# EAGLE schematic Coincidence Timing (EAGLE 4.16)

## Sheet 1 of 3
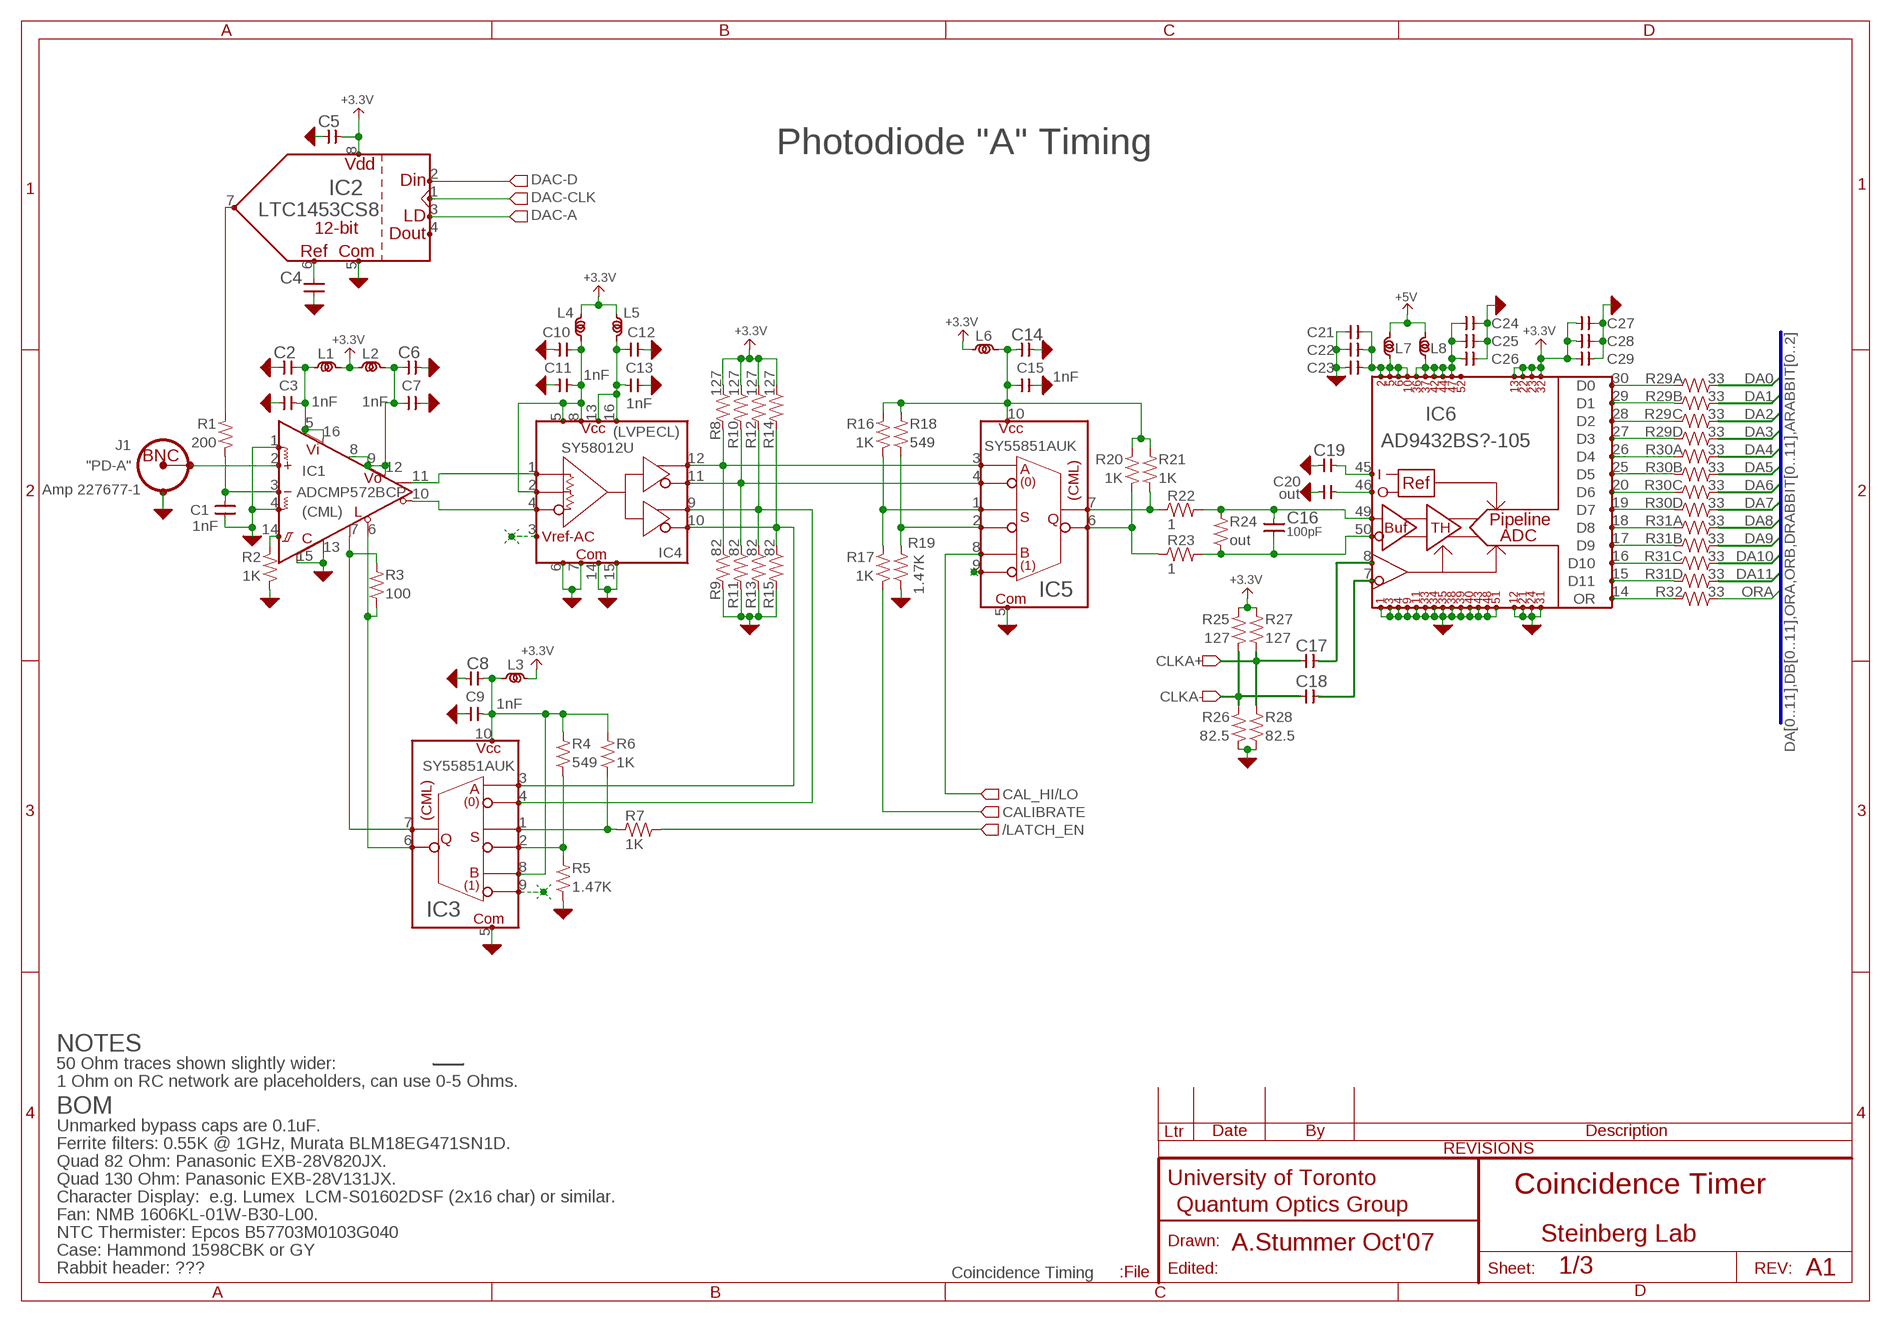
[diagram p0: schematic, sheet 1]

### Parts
C1  1nF  CAP-V-0603  [1608(0603)]
C2  CAP-H-0603  [1608(0603)]
C3  1nF  CAP-H-0603  [1608(0603)]
C4  CAP-V-0603  [1608(0603)]
C5  CAP-H-0603  [1608(0603)]
C6  CAP-H-0603  [1608(0603)]
C7  1nF  CAP-H-0603  [1608(0603)]
C8  CAP-H-0603  [1608(0603)]
C9  1nF  CAP-H-0603  [1608(0603)]
C10  CAP-H-0603  [1608(0603)]
C11  1nF  CAP-H-0603  [1608(0603)]
C12  CAP-H-0603  [1608(0603)]
C13  1nF  CAP-H-0603  [1608(0603)]
C14  CAP-H-0603  [1608(0603)]
C15  1nF  CAP-H-0603  [1608(0603)]
C16  100pF  CAP-V-0603  [1608(0603)]
C17  CAP-H-0603  [1608(0603)]
C18  CAP-H-0603  [1608(0603)]
C19  CAP-H-0603  [1608(0603)]
C20  out  CAP-H-0603  [1608(0603)]
C21  CAP-H-0603  [1608(0603)]
C22  CAP-H-0603  [1608(0603)]
C23  CAP-H-0603  [1608(0603)]
C24  CAP-H-0603  [1608(0603)]
C25  CAP-H-0603  [1608(0603)]
C26  CAP-H-0603  [1608(0603)]
C27  CAP-H-0603  [1608(0603)]
C28  CAP-H-0603  [1608(0603)]
C29  CAP-H-0603  [1608(0603)]
IC1  ADCMP572BCP  ADCMP572-3-LFCSP16  [LFCSP-16]
IC2  LTC1453CS8  LTC145_(DAC12)  [SOIC-8]
IC3  SY55851AUK  SY55851(MICREL-MUX)-MSOP10  [MSOP10]
IC4  SY58012U  SY58011-3U(MICREL_1-2BUFFER)-MLF16  [MLF-16]
IC5  SY55851AUK  SY55851(MICREL-MUX)-MSOP10  [MSOP10]
IC6  AD9432BS?-105  AD9432  [QFP52]
J1  Amp 227677-1  CONN-BNCTYPE3HORIZ  [CONN-BNC-AMP-TYPE3HORIZ]
L1  INDUCTOR-0603  [1608(0603)]
L2  INDUCTOR-0603  [1608(0603)]
L3  INDUCTOR-0603  [1608(0603)]
L4  INDUCTOR-0603  [1608(0603)]
L5  INDUCTOR-0603  [1608(0603)]
L6  INDUCTOR-0603  [1608(0603)]
L7  INDUCTOR-0603  [1608(0603)]
L8  INDUCTOR-0603  [1608(0603)]
R1  200  R-V-0603  [1608(0603)]
R2  1K  R-V-0603  [1608(0603)]
R3  100  R-V-0603  [1608(0603)]
R4  549  R-V-0603  [1608(0603)]
R5  1.47K  R-V-0603  [1608(0603)]
R6  1K  R-V-0603  [1608(0603)]
R7  1K  R-H-0603  [1608(0603)]
R8  127  R-V-0402  [1005(0402)]
R9  82  R-V-0402  [1005(0402)]
R10  127  R-V-0402  [1005(0402)]
R11  82  R-V-0402  [1005(0402)]
R12  127  R-V-0402  [1005(0402)]
R13  82  R-V-0402  [1005(0402)]
R14  127  R-V-0402  [1005(0402)]
R15  82  R-V-0402  [1005(0402)]
R16  1K  R-V-0603  [1608(0603)]
R17  1K  R-V-0603  [1608(0603)]
R18  549  R-V-0603  [1608(0603)]
R19  1.47K  R-V-0603  [1608(0603)]
R20  1K  R-V-0603  [1608(0603)]
R21  1K  R-V-0603  [1608(0603)]
R22  1  R-H-0603  [1608(0603)]
R23  1  R-H-0603  [1608(0603)]
R24  out  R-V-0603  [1608(0603)]
R25  127  R-V-0603  [1608(0603)]
R26  82.5  R-V-0603  [1608(0603)]
R27  127  R-V-0603  [1608(0603)]
R28  82.5  R-V-0603  [1608(0603)]
R29  33  R-4PAK-0603  [PANASONIC_EXB-V8V(QUAD-R-PACK)]
R30  33  R-4PAK-0603  [PANASONIC_EXB-V8V(QUAD-R-PACK)]
R31  33  R-4PAK-0603  [PANASONIC_EXB-V8V(QUAD-R-PACK)]
R32  33  R-H-0805  [2012(0805)]

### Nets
+3.3V: C5.2 C27.2 C28.2 C29.2 IC2.8(VDD) IC6.13(VCCD1) IC6.22(VCCD2) IC6.23(VCCD3) IC6.32(VCCD4) L1.2(B) L2.1(A) L3.1(A) L4.1(A) L5.1(A) L6.1(A) R8.1 R10.1 R12.1 R14.1 R25.2 R27.2 ; also sheet 2,3
+5V: L7.2(B) L8.2(B) ; also sheet 2,3
/LATCH_EN: R7.2 ; also sheet 2,3
AGND: C1.1 C2.1 C3.1 C4.1 C5.1 C6.2 C7.1 C8.2 C9.1 C10.2 C11.1 C12.2 C13.1 C14.2 C15.1 C19.1 C20.1 C21.1 C22.1 C23.1 C24.1 C25.1 C26.1 C27.1 C28.1 C29.1 IC1.1(VPT) IC1.4(VNT) IC1.13(COM1) IC1.15(COM2) IC2.5(COM) IC3.5(COM) IC4.6(COM1) IC4.7(COM2) IC4.14(COM3) IC4.15(COM4) IC5.5(COM) IC6.1(AGND1) IC6.3(AGND2) IC6.4(AGND3) IC6.9(AGND4) IC6.11(AGND5) IC6.12(DGND1) IC6.21(DGND2) IC6.24(DGND3) IC6.31(DGND4) IC6.33(AGND6) IC6.34(AGND7) IC6.35(AGND8) IC6.38(AGND9) IC6.39(AGND10) IC6.40(AGND11) IC6.43(AGND12) IC6.48(AGND13) IC6.51(AGND14) J1.SHIELD R2.1 R5.1 R9.2 R11.2 R13.2 R15.2 R19.1 R26.1 R28.1 ; also sheet 2,3
CAL_HI/LO: IC5.8(B+) ; also sheet 2,3
CALIBRATE: R17.1 ; also sheet 2,3
CLKA+ [50_Ohm]: C17.1 R27.1 R28.2 ; also sheet 3
CLKA- [50_Ohm]: C18.1 R25.1 R26.2 ; also sheet 3
DA0 [50_Ohm]: R29.1B ; also sheet 3
DA1 [50_Ohm]: R29.2B ; also sheet 3
DA2 [50_Ohm]: R29.3B ; also sheet 3
DA3 [50_Ohm]: R29.4B ; also sheet 3
DA4 [50_Ohm]: R30.1B ; also sheet 3
DA5 [50_Ohm]: R30.2B ; also sheet 3
DA6 [50_Ohm]: R30.3B ; also sheet 3
DA7 [50_Ohm]: R30.4B ; also sheet 3
DA8 [50_Ohm]: R31.1B ; also sheet 3
DA9 [50_Ohm]: R31.2B ; also sheet 3
DA10 [50_Ohm]: R31.3B ; also sheet 3
DA11 [50_Ohm]: R31.4B ; also sheet 3
DAC-A: IC2.3(CS/LD) ; also sheet 3
DAC-CLK: IC2.1(CLK) ; also sheet 2,3
DAC-D: IC2.2(DIN) ; also sheet 2,3
N$1: C1.2 IC1.3(VN) R1.1
N$2: IC1.2(VP) J1.CONDUCTOR
N$3: IC2.7(OUT) R1.2
N$4: IC3.3(A+) IC4.10(Q1-) R14.2 R15.1
N$5: C10.1 C11.2 IC4.2(INT) IC4.5(VCC1) IC4.8(VCC2) L4.2(B)
N$6: IC1.11(Q+) IC4.1(IN+)
N$7: IC1.14(HYS) R2.2
N$8: C2.2 C3.2 IC1.5(VCCI1) IC1.16(VCCI2) L1.1(A)
N$9: IC1.10(Q-) IC4.4(IN-)
N$11: C6.1 C7.2 IC1.8(VTT) IC1.9(VCCO1) IC1.12(VCCO2) L2.2(B)
N$12: IC3.4(A-) IC4.9(Q1+) R12.2 R13.1
N$13: C12.1 C13.2 IC4.13(VCC3) IC4.16(VCC4) L5.2(B)
N$14: IC1.7(LE+) IC3.7(Q+) R3.2
N$15: C14.1 C15.2 IC5.10(VCC) L6.2(B) R16.2 R18.2 R20.2 R21.2
N$16: IC5.2(S-) R18.1 R19.2
N$17 [50_Ohm]: IC5.7(Q+) R21.1 R22.1
N$18: IC1.6(LE-) IC3.6(Q-) R3.1
N$19: IC3.2(S-) R4.1 R5.2
N$20: IC3.1(S+) R6.1 R7.1
N$21: C8.1 C9.2 IC3.8(B+) IC3.10(VCC) L3.2(B) R4.2 R6.2
N$22 [50_Ohm]: IC5.6(Q-) R20.1 R23.1
N$23: IC5.1(S+) R16.1 R17.2
N$24: IC4.12(Q0+) IC5.3(A+) R8.2 R9.1
N$25: IC4.11(Q0-) IC5.4(A-) R10.2 R11.1
N$26 [50_Ohm]: C18.2 IC6.7(CLK-)
N$27 [50_Ohm]: C16.2 IC6.49(AIN+) R22.2 R24.2
N$28 [50_Ohm]: C16.1 IC6.50(AIN-) R23.2 R24.1
N$29 [50_Ohm]: C17.2 IC6.8(CLK+)
N$30: C24.2 C25.2 C26.2 IC6.36(VCCA5) IC6.37(VCCA6) IC6.42(VCCA7) IC6.44(VCCA8) IC6.52(VCCA10) L8.1(A)
N$32: C19.2 IC6.45(REF-IN)
N$33: C20.2 IC6.46(REF-OUT)
N$34: C21.2 C22.2 C23.2 IC6.2(VCCA1) IC6.5(VCCA2) IC6.6(VCCA3) IC6.10(VCCA4) L7.1(A)
N$35: IC6.30(D0) R29.1A
N$36: IC6.29(D1) R29.2A
N$37: IC6.28(D2) R29.3A
N$38: IC6.27(D3) R29.4A
N$39: IC6.26(D4) R30.1A
N$40: IC6.25(D5) R30.2A
N$41: IC6.20(D6) R30.3A
N$42: IC6.19(D7) R30.4A
N$43: IC6.18(D8) R31.1A
N$44: IC6.17(D9) R31.2A
N$45: IC6.16(D10) R31.3A
N$46: IC6.15(D11) R31.4A
N$47: C4.2 IC2.6(REF)
N$59: IC6.14(OR) R32.1
ORA: R32.2 ; also sheet 3
Unconnected: IC2.4(DOUT) IC3.9(B-) IC4.3(VREF-AC) IC5.9(B-) IC6.47(VCCA9)

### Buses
DA[0..11],DB[0..11],ORA,ORB,DRABBIT[0..11],ARABBIT[0..2]

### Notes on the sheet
- Photodiode "A" Timing
- (LVPECL)
- "PD-A"
- (CML)
- NOTES
- 50 Ohm traces shown slightly wider:
- 1 Ohm on RC network are placeholders, can use 0-5 Ohms.
- BOM
- Unmarked bypass caps are 0.1uF.
- Ferrite filters: 0.55K @ 1GHz, Murata BLM18EG471SN1D.
- Quad 82 Ohm: Panasonic EXB-28V820JX.
- Quad 130 Ohm: Panasonic EXB-28V131JX.
- Coincidence Timer
- Character Display:  e.g. Lumex  LCM-S01602DSF (2x16 char) or similar.
- Fan: NMB 1606KL-01W-B30-L00.
- NTC Thermister: Epcos B57703M0103G040 | Steinberg Lab
- A.Stummer Oct'07
- Case: Hammond 1598CBK or GY
- Rabbit header: ??? | A1

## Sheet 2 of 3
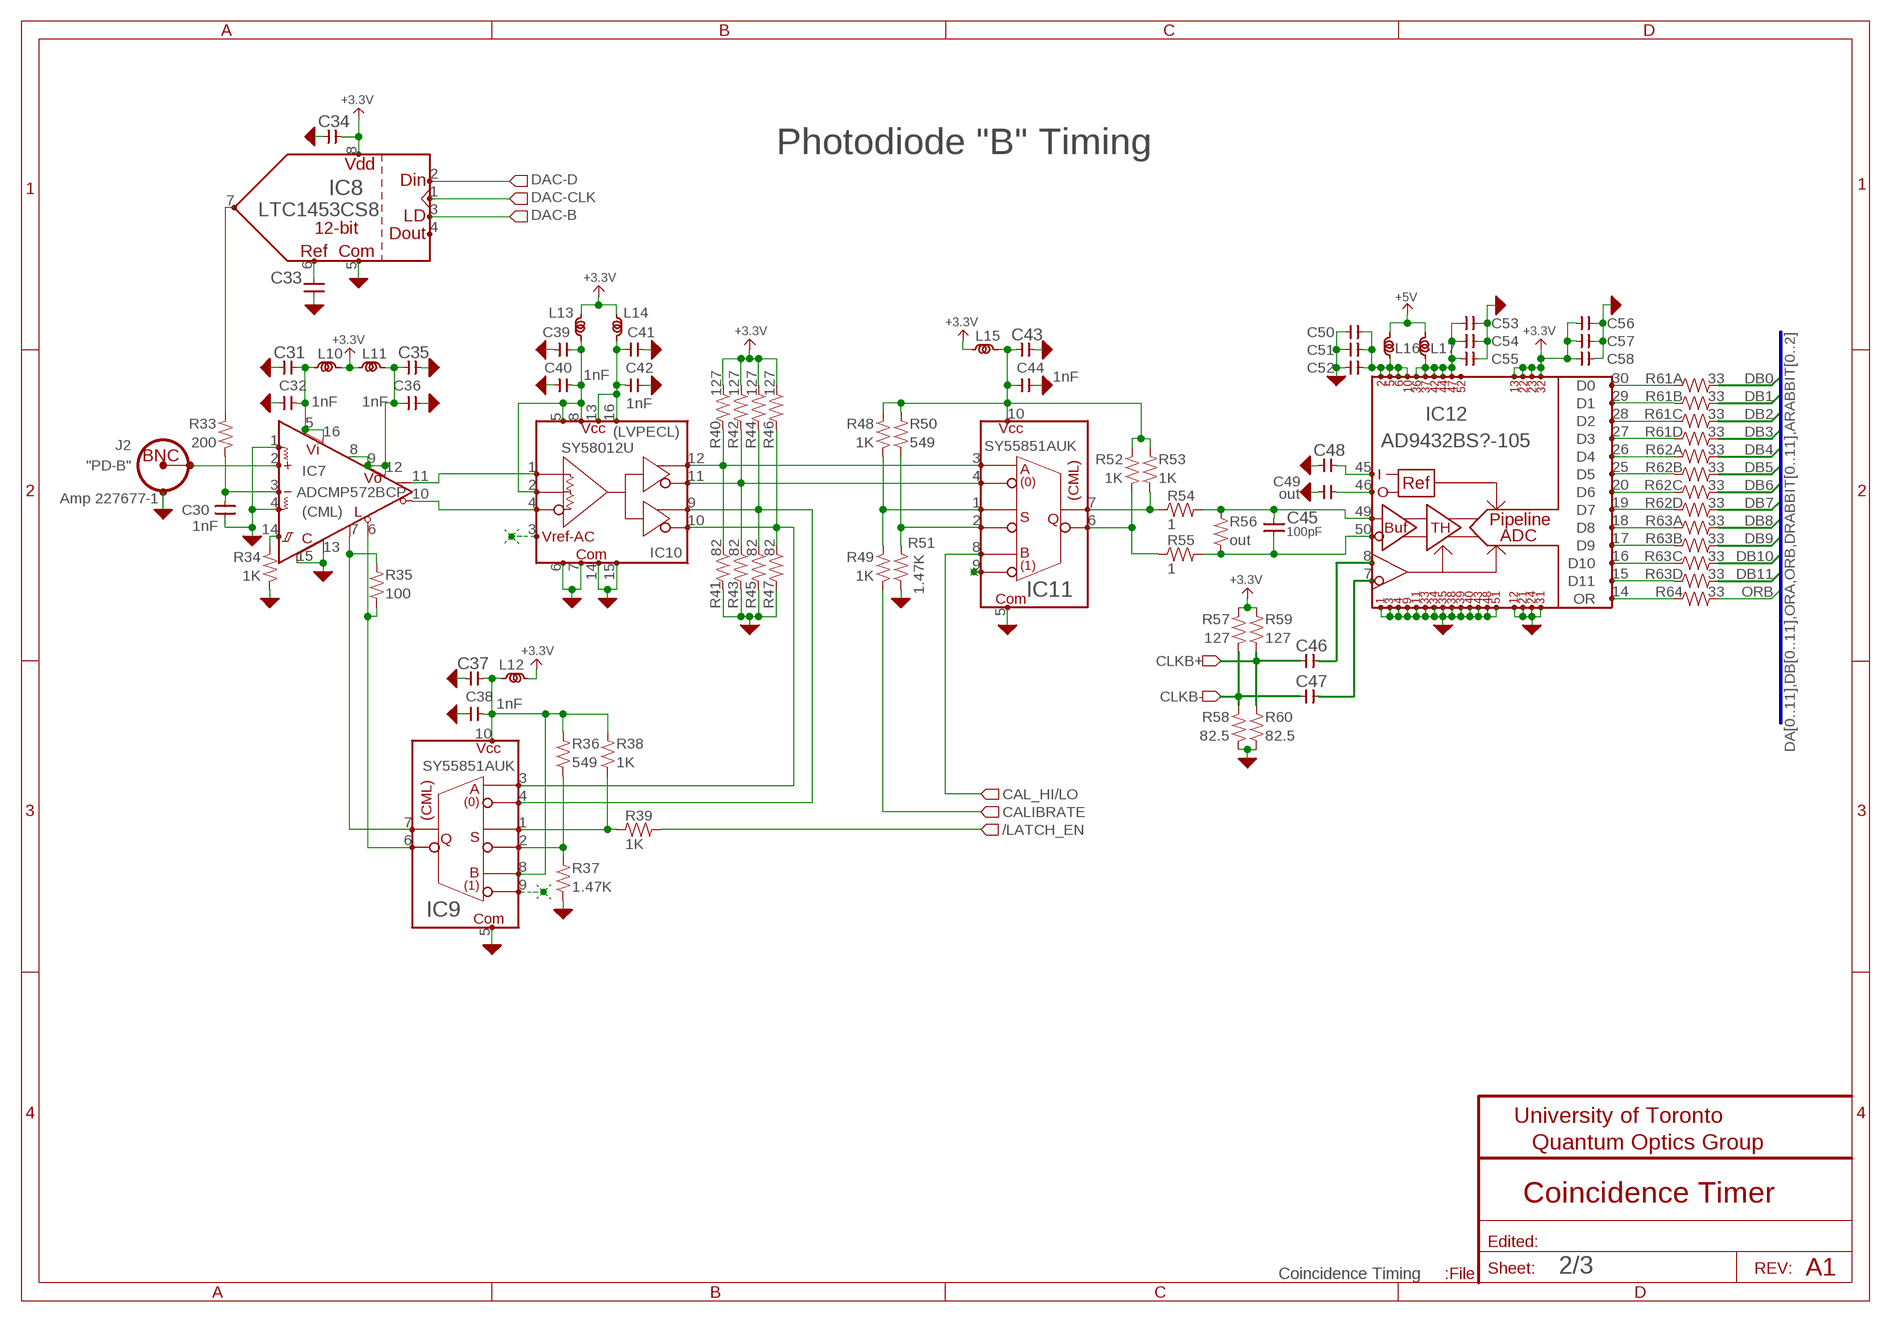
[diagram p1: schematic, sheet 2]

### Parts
C30  1nF  CAP-V-0603  [1608(0603)]
C31  CAP-H-0603  [1608(0603)]
C32  1nF  CAP-H-0603  [1608(0603)]
C33  CAP-V-0603  [1608(0603)]
C34  CAP-H-0603  [1608(0603)]
C35  CAP-H-0603  [1608(0603)]
C36  1nF  CAP-H-0603  [1608(0603)]
C37  CAP-H-0603  [1608(0603)]
C38  1nF  CAP-H-0603  [1608(0603)]
C39  CAP-H-0603  [1608(0603)]
C40  1nF  CAP-H-0603  [1608(0603)]
C41  CAP-H-0603  [1608(0603)]
C42  1nF  CAP-H-0603  [1608(0603)]
C43  CAP-H-0603  [1608(0603)]
C44  1nF  CAP-H-0603  [1608(0603)]
C45  100pF  CAP-V-0603  [1608(0603)]
C46  CAP-H-0603  [1608(0603)]
C47  CAP-H-0603  [1608(0603)]
C48  CAP-H-0603  [1608(0603)]
C49  out  CAP-H-0603  [1608(0603)]
C50  CAP-H-0603  [1608(0603)]
C51  CAP-H-0603  [1608(0603)]
C52  CAP-H-0603  [1608(0603)]
C53  CAP-H-0603  [1608(0603)]
C54  CAP-H-0603  [1608(0603)]
C55  CAP-H-0603  [1608(0603)]
C56  CAP-H-0603  [1608(0603)]
C57  CAP-H-0603  [1608(0603)]
C58  CAP-H-0603  [1608(0603)]
IC7  ADCMP572BCP  ADCMP572-3-LFCSP16  [LFCSP-16]
IC8  LTC1453CS8  LTC145_(DAC12)  [SOIC-8]
IC9  SY55851AUK  SY55851(MICREL-MUX)-MSOP10  [MSOP10]
IC10  SY58012U  SY58011-3U(MICREL_1-2BUFFER)-MLF16  [MLF-16]
IC11  SY55851AUK  SY55851(MICREL-MUX)-MSOP10  [MSOP10]
IC12  AD9432BS?-105  AD9432  [QFP52]
J2  Amp 227677-1  CONN-BNCTYPE3HORIZ  [CONN-BNC-AMP-TYPE3HORIZ]
L10  INDUCTOR-0603  [1608(0603)]
L11  INDUCTOR-0603  [1608(0603)]
L12  INDUCTOR-0603  [1608(0603)]
L13  INDUCTOR-0603  [1608(0603)]
L14  INDUCTOR-0603  [1608(0603)]
L15  INDUCTOR-0603  [1608(0603)]
L16  INDUCTOR-0603  [1608(0603)]
L17  INDUCTOR-0603  [1608(0603)]
R33  200  R-V-0603  [1608(0603)]
R34  1K  R-V-0603  [1608(0603)]
R35  100  R-V-0603  [1608(0603)]
R36  549  R-V-0603  [1608(0603)]
R37  1.47K  R-V-0603  [1608(0603)]
R38  1K  R-V-0603  [1608(0603)]
R39  1K  R-H-0603  [1608(0603)]
R40  127  R-V-0402  [1005(0402)]
R41  82  R-V-0402  [1005(0402)]
R42  127  R-V-0402  [1005(0402)]
R43  82  R-V-0402  [1005(0402)]
R44  127  R-V-0402  [1005(0402)]
R45  82  R-V-0402  [1005(0402)]
R46  127  R-V-0402  [1005(0402)]
R47  82  R-V-0402  [1005(0402)]
R48  1K  R-V-0603  [1608(0603)]
R49  1K  R-V-0603  [1608(0603)]
R50  549  R-V-0603  [1608(0603)]
R51  1.47K  R-V-0603  [1608(0603)]
R52  1K  R-V-0603  [1608(0603)]
R53  1K  R-V-0603  [1608(0603)]
R54  1  R-H-0603  [1608(0603)]
R55  1  R-H-0603  [1608(0603)]
R56  out  R-V-0603  [1608(0603)]
R57  127  R-V-0603  [1608(0603)]
R58  82.5  R-V-0603  [1608(0603)]
R59  127  R-V-0603  [1608(0603)]
R60  82.5  R-V-0603  [1608(0603)]
R61  33  R-4PAK-0603  [PANASONIC_EXB-V8V(QUAD-R-PACK)]
R62  33  R-4PAK-0603  [PANASONIC_EXB-V8V(QUAD-R-PACK)]
R63  33  R-4PAK-0603  [PANASONIC_EXB-V8V(QUAD-R-PACK)]
R64  33  R-H-0805  [2012(0805)]

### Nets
+3.3V: C34.2 C56.2 C57.2 C58.2 IC8.8(VDD) IC12.13(VCCD1) IC12.22(VCCD2) IC12.23(VCCD3) IC12.32(VCCD4) L10.2(B) L11.1(A) L12.1(A) L13.1(A) L14.1(A) L15.1(A) R40.1 R42.1 R44.1 R46.1 R57.2 R59.2 ; also sheet 1,3
+5V: L16.2(B) L17.2(B) ; also sheet 1,3
/LATCH_EN: R39.2 ; also sheet 1,3
AGND: C30.1 C31.1 C32.1 C33.1 C34.1 C35.2 C36.1 C37.2 C38.1 C39.2 C40.1 C41.2 C42.1 C43.2 C44.1 C48.1 C49.1 C50.1 C51.1 C52.1 C53.1 C54.1 C55.1 C56.1 C57.1 C58.1 IC7.1(VPT) IC7.4(VNT) IC7.13(COM1) IC7.15(COM2) IC8.5(COM) IC9.5(COM) IC10.6(COM1) IC10.7(COM2) IC10.14(COM3) IC10.15(COM4) IC11.5(COM) IC12.1(AGND1) IC12.3(AGND2) IC12.4(AGND3) IC12.9(AGND4) IC12.11(AGND5) IC12.12(DGND1) IC12.21(DGND2) IC12.24(DGND3) IC12.31(DGND4) IC12.33(AGND6) IC12.34(AGND7) IC12.35(AGND8) IC12.38(AGND9) IC12.39(AGND10) IC12.40(AGND11) IC12.43(AGND12) IC12.48(AGND13) IC12.51(AGND14) J2.SHIELD R34.1 R37.1 R41.2 R43.2 R45.2 R47.2 R51.1 R58.1 R60.1 ; also sheet 1,3
CAL_HI/LO: IC11.8(B+) ; also sheet 1,3
CALIBRATE: R49.1 ; also sheet 1,3
CLKB+ [50_Ohm]: C46.1 R59.1 R60.2 ; also sheet 3
CLKB- [50_Ohm]: C47.1 R57.1 R58.2 ; also sheet 3
DAC-B: IC8.3(CS/LD) ; also sheet 3
DAC-CLK: IC8.1(CLK) ; also sheet 1,3
DAC-D: IC8.2(DIN) ; also sheet 1,3
DB0: R61.1B ; also sheet 3
DB1: R61.2B ; also sheet 3
DB2: R61.3B ; also sheet 3
DB3: R61.4B ; also sheet 3
DB4: R62.1B ; also sheet 3
DB5: R62.2B ; also sheet 3
DB6: R62.3B ; also sheet 3
DB7: R62.4B ; also sheet 3
DB8: R63.1B ; also sheet 3
DB9: R63.2B ; also sheet 3
DB10: R63.3B ; also sheet 3
DB11: R63.4B ; also sheet 3
N$10: IC9.3(A+) IC10.10(Q1-) R46.2 R47.1
N$69: IC9.4(A-) IC10.9(Q1+) R44.2 R45.1
N$71: IC7.2(VP) J2.CONDUCTOR
N$74: C30.2 IC7.3(VN) R33.1
N$75: IC7.14(HYS) R34.2
N$76: C31.2 C32.2 IC7.5(VCCI1) IC7.16(VCCI2) L10.1(A)
N$77: C35.1 C36.2 IC7.8(VTT) IC7.9(VCCO1) IC7.12(VCCO2) L11.2(B)
N$78: C39.1 C40.2 IC10.2(INT) IC10.5(VCC1) IC10.8(VCC2) L13.2(B)
N$79: C41.1 C42.2 IC10.13(VCC3) IC10.16(VCC4) L14.2(B)
N$80: IC7.11(Q+) IC10.1(IN+)
N$81: IC7.10(Q-) IC10.4(IN-)
N$85: IC7.7(LE+) IC9.7(Q+) R35.2
N$86: IC7.6(LE-) IC9.6(Q-) R35.1
N$87: IC9.2(S-) R36.1 R37.2
N$88: IC9.1(S+) R38.1 R39.1
N$89: C37.1 C38.2 IC9.8(B+) IC9.10(VCC) L12.2(B) R36.2 R38.2
N$90: IC11.2(S-) R50.1 R51.2
N$91: IC11.1(S+) R48.1 R49.2
N$92: IC10.12(Q0+) IC11.3(A+) R40.2 R41.1
N$93: IC10.11(Q0-) IC11.4(A-) R42.2 R43.1
N$94 [50_Ohm]: IC11.7(Q+) R53.1 R54.1
N$95 [50_Ohm]: IC11.6(Q-) R52.1 R55.1
N$96 [50_Ohm]: C45.2 IC12.49(AIN+) R54.2 R56.2
N$97 [50_Ohm]: C45.1 IC12.50(AIN-) R55.2 R56.1
N$98: C43.1 C44.2 IC11.10(VCC) L15.2(B) R48.2 R50.2 R52.2 R53.2
N$99: C53.2 C54.2 C55.2 IC12.36(VCCA5) IC12.37(VCCA6) IC12.42(VCCA7) IC12.44(VCCA8) IC12.52(VCCA10) L17.1(A)
N$100 [50_Ohm]: C47.2 IC12.7(CLK-)
N$101 [50_Ohm]: C46.2 IC12.8(CLK+)
N$102: C48.2 IC12.45(REF-IN)
N$103: C49.2 IC12.46(REF-OUT)
N$104: C50.2 C51.2 C52.2 IC12.2(VCCA1) IC12.5(VCCA2) IC12.6(VCCA3) IC12.10(VCCA4) L16.1(A)
N$106: IC12.30(D0) R61.1A
N$107: IC12.29(D1) R61.2A
N$108: IC12.28(D2) R61.3A
N$109: IC12.27(D3) R61.4A
N$110: IC12.26(D4) R62.1A
N$111: IC12.25(D5) R62.2A
N$112: IC12.20(D6) R62.3A
N$113: IC12.19(D7) R62.4A
N$114: IC12.18(D8) R63.1A
N$115: IC12.17(D9) R63.2A
N$116: IC12.16(D10) R63.3A
N$117: IC12.15(D11) R63.4A
N$118: IC8.7(OUT) R33.2
N$119: C33.2 IC8.6(REF)
N$120: IC12.14(OR) R64.1
ORB: R64.2 ; also sheet 3
Unconnected: IC8.4(DOUT) IC9.9(B-) IC10.3(VREF-AC) IC11.9(B-) IC12.47(VCCA9)

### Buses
DA[0..11],DB[0..11],ORA,ORB,DRABBIT[0..11],ARABBIT[0..2]

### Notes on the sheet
- Photodiode "B" Timing
- (LVPECL)
- "PD-B"
- (CML)
- Coincidence Timer
- A1

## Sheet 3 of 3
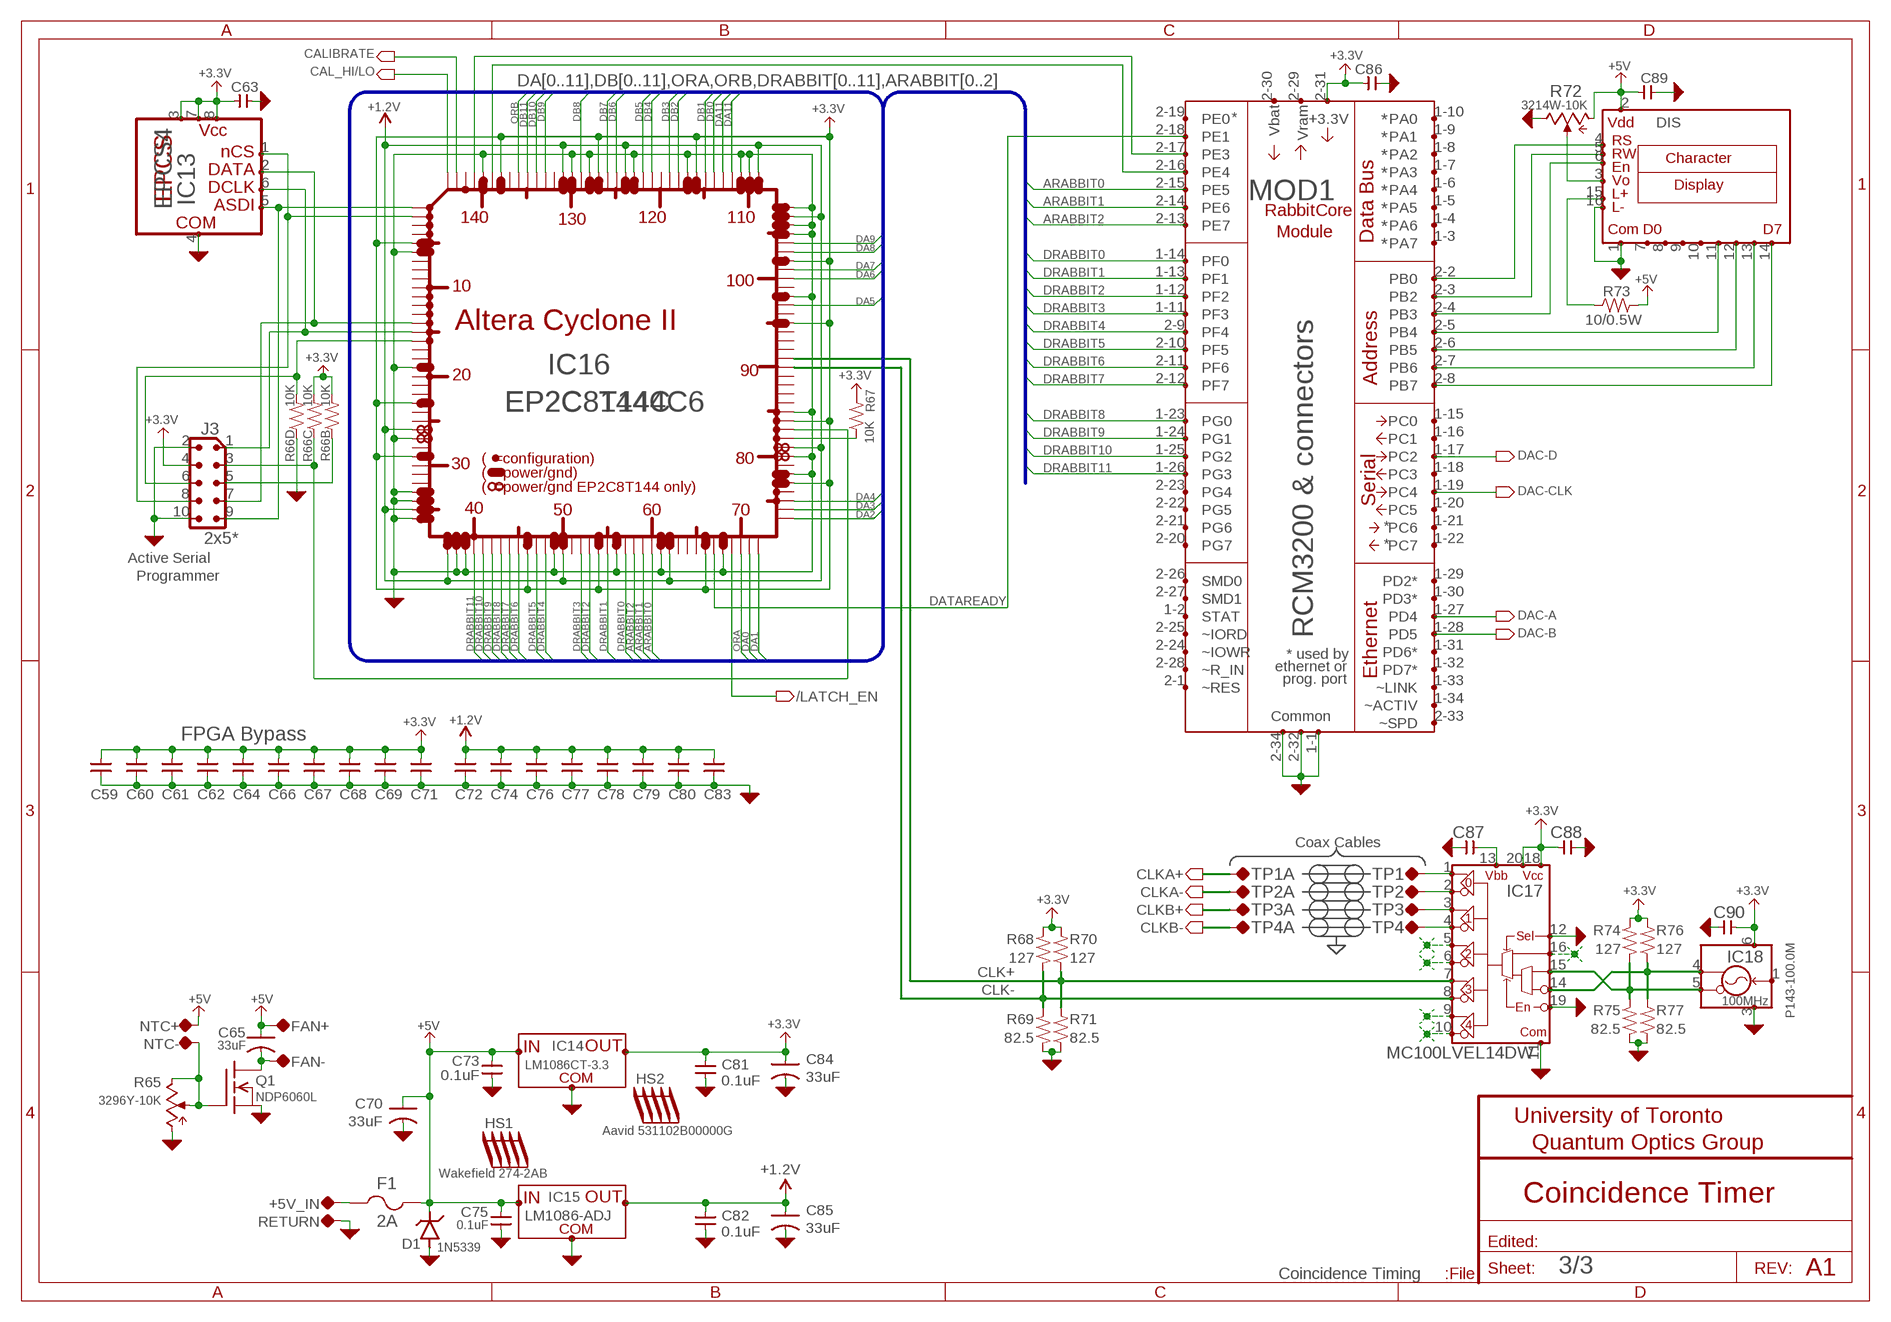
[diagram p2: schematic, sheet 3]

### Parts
+5V_IN  TP-0.042"  [TP-0.042]
C59  CAP-V-0603  [1608(0603)]
C60  CAP-V-0603  [1608(0603)]
C61  CAP-V-0603  [1608(0603)]
C62  CAP-V-0603  [1608(0603)]
C63  CAP-H-0603  [1608(0603)]
C64  CAP-V-0603  [1608(0603)]
C65  33uF  CAP-POL-6032  [EIA-6032]
C66  CAP-V-0603  [1608(0603)]
C67  CAP-V-0603  [1608(0603)]
C68  CAP-V-0603  [1608(0603)]
C69  CAP-V-0603  [1608(0603)]
C70  33uF  CAP-POL-6032  [EIA-6032]
C71  CAP-V-0603  [1608(0603)]
C72  CAP-V-0603  [1608(0603)]
C73  0.1uF  CAP-V-0603  [1608(0603)]
C74  CAP-V-0603  [1608(0603)]
C75  0.1uF  CAP-V-0603  [1608(0603)]
C76  CAP-V-0603  [1608(0603)]
C77  CAP-V-0603  [1608(0603)]
C78  CAP-V-0603  [1608(0603)]
C79  CAP-V-0603  [1608(0603)]
C80  CAP-V-0603  [1608(0603)]
C81  0.1uF  CAP-V-0603  [1608(0603)]
C82  0.1uF  CAP-V-0603  [1608(0603)]
C83  CAP-V-0603  [1608(0603)]
C84  33uF  CAP-POL-6032  [EIA-6032]
C85  33uF  CAP-POL-6032  [EIA-6032]
C86  CAP-H-0805  [2012(0805)]
C87  CAP-H-0603  [1608(0603)]
C88  CAP-H-0603  [1608(0603)]
C89  CAP-H-0805  [2012(0805)]
C90  CAP-H-0603  [1608(0603)]
D1  1N5339  ZENER-THROUGH-0.4"  [PASSIVE_0.4"]
DIS  DISPLAY1  [DISPLAY1]
F1  2A  FUSE-5X20-4  [FUSE]
FAN+  TP-0.042"  [TP-0.042]
FAN-  TP-0.042"  [TP-0.042]
HS1  Wakefield 274-2AB  HEATSINK1-274AB  [HEATSINK-3]
HS2  Aavid 531102B00000G  HEATSINK1529802...  [HEATSINK_529802B02(AAVID)]
IC13  EPCS4  EPCS1-4(ALTERA_CONFIG)  [SOIC-8]
IC14  LM1086CT-3.3  LM1086-TO220(VERTICAL)  [TO220-VERTICAL]
IC15  LM1086-ADJ  LM1086-TO263  [TO263]
IC16  EP2C8T144C6  ALTERA-EP2C_T144C_  [TQFP-144]
IC17  MC100LVEL14DW  MC100LVEL14-SOIC20  [SOIC-20W]
IC18  P143-100.0M  OSC_1_PECL  [CONNER-WINFIELD_6]
J3  2x5*  CONN-2X5-BLASTER  [CONN-2X5-BLASTER]
MOD1  RCM3200 & connectors  RABBIT_RCM3XXX  [RABBIT_RCM3XXX]
NTC+  TP-0.042"  [TP-0.042]
NTC-  TP-0.042"  [TP-0.042]
Q1  NDP6060L  MOSFET-N-TO220-VERT  [TO220-VERTICAL]
R65  3296Y-10K  POTBOURNS_3296Y  [BOURNS-3296Y]
R66  10K  R-4PAK-0603  [PANASONIC_EXB-V8V(QUAD-R-PACK)]
R67  10K  R-V-0603  [1608(0603)]
R68  127  R-V-0603  [1608(0603)]
R69  82.5  R-V-0603  [1608(0603)]
R70  127  R-V-0603  [1608(0603)]
R71  82.5  R-V-0603  [1608(0603)]
R72  3214W-10K  POT-3214W_TRIM  [BOURNS_3214]
R73  10/0.5W  R-H-THRU  [PASSIVE_0.4"]
R74  127  R-V-0603  [1608(0603)]
R75  82.5  R-V-0603  [1608(0603)]
R76  127  R-V-0603  [1608(0603)]
R77  82.5  R-V-0603  [1608(0603)]
RETURN  TP-0.042"  [TP-0.042]
TP1  TP-0.042"  [TP-0.042]
TP1A  TP-0.042"  [TP-0.042]
TP2  TP-0.042"  [TP-0.042]
TP2A  TP-0.042"  [TP-0.042]
TP3  TP-0.042"  [TP-0.042]
TP3A  TP-0.042"  [TP-0.042]
TP4  TP-0.042"  [TP-0.042]
TP4A  TP-0.042"  [TP-0.042]

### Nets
+1.2V: C72.2 C74.2 C76.2 C77.2 C78.2 C79.2 C80.2 C82.2 C83.2 C85.+(POS) IC15.2(OUT) IC16.26 IC16.35 IC16.37 IC16.50 IC16.62 IC16.81 IC16.107 IC16.109 IC16.124 IC16.131
+3.3V: C59.2 C60.2 C61.2 C62.2 C63.1 C64.2 C66.2 C67.2 C68.2 C69.2 C71.2 C81.2 C84.+(POS) C86.2 C88.2 C90.2 IC13.3(VCC1) IC13.7(VCC2) IC13.8(VCC3) IC14.2(OUT) IC16.5 IC16.23 IC16.29 IC16.46 IC16.54 IC16.66 IC16.77 IC16.84 IC16.95 IC16.102 IC16.116 IC16.127 IC16.138 IC17.18(VCC1) IC17.20(VCC2) IC18.6(VCC) J3.4 MOD1.2-31(+3.3V) R66.2B R66.3B R67.2 R68.2 R70.2 R74.2 R76.2 ; also sheet 1,2
+5V: C65.+(POS) C70.+(POS) C73.2 C75.2 C89.2 D1.2(C) DIS.2(VDD) F1.1A FAN+.TP IC14.3(VI) IC15.3(VI) NTC+.TP R72.CCW R73.2 ; also sheet 1,2
/LATCH_EN: IC16.69 ; also sheet 1,2
AGND: C59.1 C60.1 C61.1 C62.1 C63.2 C64.1 C66.1 C67.1 C68.1 C69.1 C70.-(NEG) C71.1 C72.1 C73.1 C74.1 C75.1 C76.1 C77.1 C78.1 C79.1 C80.1 C81.1 C82.1 C83.1 C84.-(NEG) C85.-(NEG) C86.1 C87.2 C88.1 C89.1 C90.1 D1.1(A) DIS.1(VSS) DIS.16(LED-) IC13.4(COM) IC14.1(COM) IC15.1(COM) IC16.6 IC16.19 IC16.27 IC16.33 IC16.34 IC16.36 IC16.38 IC16.39 IC16.49 IC16.56 IC16.61 IC16.68 IC16.78 IC16.80 IC16.85 IC16.98 IC16.105 IC16.106 IC16.108 IC16.110 IC16.111 IC16.117 IC16.123 IC16.128 IC16.130 IC16.140 IC17.11(VEE) IC17.12(SEL) IC17.19(~EN) IC18.3(COM) J3.2 J3.10 MOD1.1-1(GND1) MOD1.2-32(GND2) MOD1.2-34(GND3) Q1.3(S) R65.CCW R66.4A R69.1 R71.1 R72.CW R75.1 R77.1 RETURN.TP ; also sheet 1,2
ARABBIT0: IC16.60 MOD1.2-15(PE5)
ARABBIT1: IC16.59 MOD1.2-14(PE6)
ARABBIT2: IC16.58 MOD1.2-13(PE7)
CAL_HI/LO: IC16.144 ; also sheet 1,2
CALIBRATE: IC16.143 ; also sheet 1,2
CLK+ [50_Ohm]: IC16.91 IC17.7(Q3+) R70.1 R71.2
CLK- [50_Ohm]: IC16.90 IC17.8(Q3-) R68.1 R69.2
CLKA+ [50_Ohm]: TP1A.TP ; also sheet 1
CLKA- [50_Ohm]: TP2A.TP ; also sheet 1
CLKB+ [50_Ohm]: TP3A.TP ; also sheet 2
CLKB- [50_Ohm]: TP4A.TP ; also sheet 2
DA0 [50_Ohm]: IC16.71 ; also sheet 1
DA1 [50_Ohm]: IC16.72 ; also sheet 1
DA2 [50_Ohm]: IC16.73 ; also sheet 1
DA3 [50_Ohm]: IC16.74 ; also sheet 1
DA4 [50_Ohm]: IC16.75 ; also sheet 1
DA5 [50_Ohm]: IC16.97 ; also sheet 1
DA6 [50_Ohm]: IC16.100 ; also sheet 1
DA7 [50_Ohm]: IC16.101 ; also sheet 1
DA8 [50_Ohm]: IC16.103 ; also sheet 1
DA9 [50_Ohm]: IC16.104 ; also sheet 1
DA10 [50_Ohm]: IC16.112 ; also sheet 1
DA11 [50_Ohm]: IC16.113 ; also sheet 1
DAC-A: MOD1.1-27(PD4) ; also sheet 1
DAC-B: MOD1.1-28(PD5) ; also sheet 2
DAC-CLK: MOD1.1-19(PC4) ; also sheet 1,2
DAC-D: MOD1.1-17(PC2) ; also sheet 1,2
DATAREADY: IC16.67 MOD1.2-18(PE1)
DB0: IC16.114 ; also sheet 2
DB1: IC16.115 ; also sheet 2
DB2: IC16.118 ; also sheet 2
DB3: IC16.119 ; also sheet 2
DB4: IC16.121 ; also sheet 2
DB5: IC16.122 ; also sheet 2
DB6: IC16.125 ; also sheet 2
DB7: IC16.126 ; also sheet 2
DB8: IC16.129 ; also sheet 2
DB9: IC16.133 ; also sheet 2
DB10: IC16.134 ; also sheet 2
DB11: IC16.135 ; also sheet 2
DRABBIT0: IC16.57 MOD1.1-14(PF0)
DRABBIT1: IC16.55 MOD1.1-13(PF1)
DRABBIT2: IC16.53 MOD1.1-12(PF2)
DRABBIT3: IC16.52 MOD1.1-11(PF3)
DRABBIT4: IC16.48 MOD1.2-9(PF4)
DRABBIT5: IC16.47 MOD1.2-10(PF5)
DRABBIT6: IC16.45 MOD1.2-11(PF6)
DRABBIT7: IC16.44 MOD1.2-12(PF7)
DRABBIT8: IC16.43 MOD1.1-23(PG0)
DRABBIT9: IC16.42 MOD1.1-24(PG1)
DRABBIT10: IC16.41 MOD1.1-25(PG2)
DRABBIT11: IC16.40 MOD1.1-26(PG3)
N$31: IC16.141 MOD1.2-17(PE3)
N$48 [50_Ohm]: IC17.14(CLK-) IC18.4(Q+) R76.1 R77.2
N$49 [50_Ohm]: IC17.15(CLK+) IC18.5(Q-) R74.1 R75.2
N$50: C87.1 IC17.13(VBB)
N$51: IC13.2(DATA) IC16.14 J3.7
N$52: IC13.6(DCLK) IC16.15 J3.1
N$53: IC13.5(ASDI) IC16.1 J3.9
N$54: IC13.1(NCS) IC16.2 J3.8
N$55: IC16.83 J3.3 R66.3A
N$56: J3.5 R66.2A
N$57: IC16.16 J3.6 R66.4B
N$58: IC16.82 R67.1
N$60: +5V_IN.TP F1.2A
N$61: DIS.14(D7) MOD1.2-8(PB7)
N$62: DIS.13(D6) MOD1.2-7(PB6)
N$63: DIS.12(D5) MOD1.2-6(PB5)
N$64: DIS.11(D4) MOD1.2-5(PB4)
N$65: DIS.6(EN) MOD1.2-4(PB3)
N$66: DIS.5(RW) MOD1.2-3(PB2)
N$67: DIS.4(RS) MOD1.2-2(PB0)
N$68: DIS.3(VO) R72.W
N$70: DIS.15(LED+) R73.1
N$72: IC16.139 MOD1.2-16(PE4)
N$73: C65.-(NEG) FAN-.TP Q1.2(D)
N$82: IC17.1(Q0+) TP1.TP
N$83: IC17.2(Q0-) TP2.TP
N$84: IC17.3(Q1+) TP3.TP
N$121: IC17.4(Q1-) TP4.TP
N$122: NTC-.TP Q1.1(G) R65.CW R65.W
ORA: IC16.70 ; also sheet 1
ORB: IC16.136 ; also sheet 2
Unconnected: DIS.7(D0) DIS.8(D1) DIS.9(D2) DIS.10(D3) IC16.3 IC16.4 IC16.7 IC16.8 IC16.9 IC16.10 IC16.11 IC16.12 IC16.13 IC16.17 IC16.18 IC16.20 IC16.21 IC16.22 IC16.24 IC16.25 IC16.28 IC16.30 IC16.31 IC16.32 IC16.51 IC16.63 IC16.64 IC16.65 IC16.76 IC16.79 IC16.86 IC16.87 IC16.88 IC16.89 IC16.92 IC16.93 IC16.94 IC16.96 IC16.99 IC16.120 IC16.132 IC16.137 IC16.142 IC17.5(Q2+) IC17.6(Q2-) IC17.9(Q4+) IC17.10(Q4-) IC17.16(SCLK) IC18.1(EN) MOD1.1-2(STAT) MOD1.1-3(PA7) MOD1.1-4(PA6) MOD1.1-5(PA5) MOD1.1-6(PA4) MOD1.1-7(PA3) MOD1.1-8(PA2) MOD1.1-9(PA1) MOD1.1-10(PA0) MOD1.1-15(PC0) MOD1.1-16(PC1) MOD1.1-18(PC3) MOD1.1-20(PC5) MOD1.1-21(PC6) MOD1.1-22(PC7) MOD1.1-29(PD2*) MOD1.1-30(PD3*) MOD1.1-31(PD6*) MOD1.1-32(PD7*) MOD1.1-33(~LINK) MOD1.1-34(~ACTIV) MOD1.2-1(~RES) MOD1.2-19(PE0) MOD1.2-20(PG7) MOD1.2-21(PG6) MOD1.2-22(PG5) MOD1.2-23(PG4) MOD1.2-24(~IOWR) MOD1.2-25(~IORD) MOD1.2-26(SMD0) MOD1.2-27(SMD1) MOD1.2-28(~R_IN) MOD1.2-29(VRAM) MOD1.2-30(VBAT_EXT) MOD1.2-33(~SPD) R66.1A R66.1B

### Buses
DA[0..11],DB[0..11],ORA,ORB,DRABBIT[0..11],ARABBIT[0..2]

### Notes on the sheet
- Active Serial
- Programmer
- FPGA Bypass
- Coax Cables
- 100MHz
- Coincidence Timer
- A1

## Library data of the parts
+5V_IN FAN+ FAN- NTC+ NTC- RETURN TP1 TP1A TP2 TP2A TP3 TP3A TP4 TP4A = QuantumOptics:TP: Testpoint, test point on schematic, on PCB either SMT pad, small hole or loop style TP.
C1 C4 C16 C30 C33 C45 C59-C62 C64 C66-C69 C71-C83 = QuantumOptics:CAP-V-: Cap, SMT and Through-hole, 0402 and up.
C2 C3 C5-C15 C17-C29 C31 C32 C34-C44 C46-C58 C63 C86-C90 = QuantumOptics:CAP-H-: Cap, SMT and Through-hole, 0402 and up.
C65 C70 C84 C85 = QuantumOptics:CAP-POL-: Capacitor, Polarized, SMT 0805 and up, probably tantalum.
D1 = QuantumOptics:ZENER: Zener
DIS = QuantumOptics:DISPLAY1: LCD Character Display #1, actually just a line of holes for ribbin cable. All LCD modules are variations on a theme so this applies to most. Based on http://rocky.digikey.com/WebLib/Varitronix/Web%20Data/MDL(S)-16265.pdf
F1 = QuantumOptics:FUSE: Fuse
HS1 HS2 = QuantumOptics:HEATSINK1: Heatsink, no connections to heatsink.
IC1 IC7 = QuantumOptics:ADCMP572-3: ADCMP572-3 Comparator, Analog Devices, PECL/CML, 150pS. e.g. http://www.analog.com/UploadedFiles/Data_Sheets/ADCMP572_573.pdf
IC2 IC8 = QuantumOptics:LTC145_(DAC12): LTC145x, 12-bit SPI DAC, Linear Technology, int/ext ref, single supply, SO-8. http://www.linear.com/pc/downloadDocument.do?navId=H0,C1,C1155,C1005,C1156,P1017,D3265
IC3 IC5 IC9 IC11 = QuantumOptics:SY55851(MICREL-MUX): SY55851(A), Mux, Micrel, CML outputs, 3GHz, AND/OR/XOR. http://www.micrel.com/_PDF/HBW/sy55851-51a.pdf
IC4 IC10 = QuantumOptics:SY58011-3U(MICREL_1-2BUFFER): SY58011U -2U- 3U, 1:2 Buffer, Micrel, CML/LVPECL/RSLVPECL, Tr=60pS, 6GHz. http://www.micrel.com/_PDF/HBW/sy58011u.pdf. http://www.micrel.com/_PDF/HBW/sy58012u.pdf. http://www.micrel.com/_PDF/HBW/sy58013u.pdf.
IC6 IC12 = QuantumOptics:AD9432: AD9432, fast 12-bit ADC, AnaDev, 85/105MSPS, parallel CMOS/TTL, easy to use. http://www.analog.com/en/prod/0,,AD9432,00.html
IC13 = QuantumOptics:EPCS1-4(ALTERA_CONFIG): EPCS1 or EPCS4, Altera, FPGA serial configuration device.
IC14 IC15 = QuantumOptics:LM1086: LM1086-xxx, National Semiconductor, LDO, adjustable or fixed. http://cache.national.com/ds/LM/LM1086.pdf
IC16 = QuantumOptics:ALTERA-EP2C_T144C_: Altera FPGA EP2C[5|8]T144Cx, Cyclone II, EP2C5T144Cx or EP2C8T144Cx, where x is speed grade. http://www.altera.com/literature/lit-cyc2.jsp
IC17 = QuantumOptics:MC100LVEL14: MC100LVEL14, 1:5 Clock Distribution, 3.3V but also MC100EL14 for 5V. Based on http://www.onsemi.com/pub/Collateral/MC100LVEL14-D.PDF
IC18 = QuantumOptics:OSC_1_PECL: Oscillator, PECL, Conner-Winfield Pxxx-xxx series http://www.conwin.com/datasheets/ec/ec217.pdf
J1 J2 = QuantumOptics:CONN-BNC: BNC PCB connectorsUses 0.1" grid.
J3 = QuantumOptics:CONN-2X5-BLASTER: Connector, 2 rows of 5 for ByteBlaster, USBBlaster or MasterBlaster, on 0.1" grid, pins numbering zig-zags top-left to bottom-right.
L1-L8 L10-L17 = QuantumOptics:INDUCTOR: Inductor, generic inductor.
MOD1 = QuantumOptics:RABBIT_RCM3XXX: Rabbit RCM3xxx Module, Rabbit module with ethernet. Remember connectors Sullins PPPN172AFCN (S5750-17-ND). http://www.zworld.com/documentation/docs/manuals/RCM3000/UsersManual/index.htm http://www.zworld.com/documentation/docs/manuals/RCM3000/UsersManual/RC3000UM.pdf Connector Sullin Electronics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
Q1 = QuantumOptics:MOSFET-N: Mosfet, N-Channel, generic enhancement mode N-FET.
R1-R6 R8-R21 R24-R28 R33-R38 R40-R53 R56-R60 R67-R71 R74-R77 = QuantumOptics:R-V-*: Resistor, SMT & Through-Hole, vertical symbol
R7 R22 R23 R32 R39 R54 R55 R64 R73 = QuantumOptics:R-H-*: Resistor, SMT & Through-Hole, horizontal symbol
R29-R31 R61-R63 R66 = QuantumOptics:R-4PAK: Quad Resistor Pack
R65 R72 = QuantumOptics:POT: Pot, regular or trimpot

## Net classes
0 default: clearance 0.406 mm
1 50_Ohm: width 0.178 mm, drill 0.178 mm, clearance 0.406 mm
